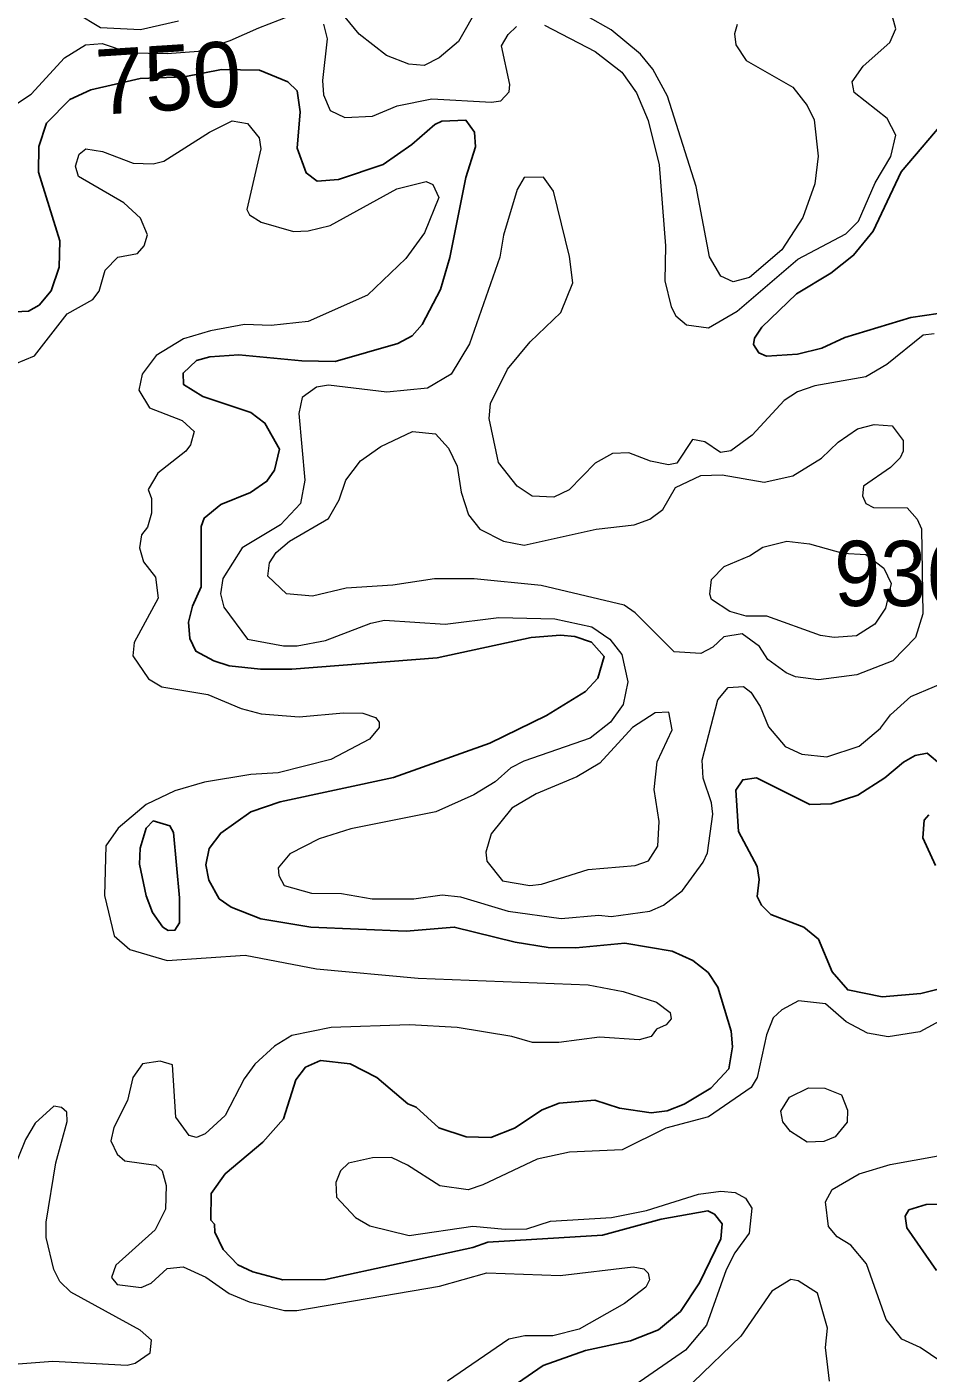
# Model space of a CAD drawing. Extents: x 763.2 to 816.8, y 7896.5 to 7952.7.
# Drawn here: x 772.488 to 774.699, y 7913.666 to 7916.968 of the extents above; entities that cross this region are included whole.
import ezdxf
from ezdxf.enums import TextEntityAlignment as Align

# ---------------------------------------------------------------- set-up
doc = ezdxf.new("R2010")
doc.units = 0
doc.header["$LTSCALE"] = 0.064
doc.layers.add('1', color=7, linetype='Continuous', lineweight=25)
doc.layers.add('2', color=7, linetype='Continuous', lineweight=13)
doc.layers.add('21', color=7, linetype='Continuous')
doc.layers.add('61', color=7, linetype='Continuous')

msp = doc.modelspace()

# ---------------------------------------------------------------- linework, layer by layer
at = {"layer": '1'}
for points in [[(772.8943, 7915.5473), (772.9158, 7915.595), (772.9157, 7915.7428), (772.9231, 7915.7635), (772.9643, 7915.7966), (773.0365, 7915.8265), (773.077, 7915.8539), (773.0953, 7915.881), (773.1079, 7915.9322), (773.0723, 7915.9965), (773.038, 7916.0226), (772.9197, 7916.0616), (772.8726, 7916.091), (772.8715, 7916.1192), (772.9045, 7916.1496), (772.937, 7916.1588), (773.0084, 7916.1635), (773.1629, 7916.1488), (773.2442, 7916.1477), (773.3981, 7916.1913), (773.4337, 7916.2102), (773.4581, 7916.2382), (773.5025, 7916.3238), (773.5254, 7916.4027), (773.5647, 7916.5984), (773.5891, 7916.674), (773.5861, 7916.7101), (773.5651, 7916.739), (773.506, 7916.7366), (773.4886, 7916.7289), (773.4327, 7916.6793), (773.3619, 7916.6302), (773.2529, 7916.5938), (773.2, 7916.5901), (773.1734, 7916.6098), (773.1511, 7916.6709), (773.1588, 7916.7595), (773.1517, 7916.8111), (773.1281, 7916.8336), (773.0593, 7916.8617), (772.9659, 7916.8637), (772.8745, 7916.8459), (772.7663, 7916.8417), (772.6452, 7916.8141), (772.5934, 7916.7901), (772.5363, 7916.7318), (772.518, 7916.6747), (772.5166, 7916.6119), (772.5689, 7916.4431), (772.5672, 7916.379), (772.5476, 7916.3204), (772.5182, 7916.2858), (772.492, 7916.271), (772.4595, 7916.2689)], [(774.7493, 7916.7498), (774.6331, 7916.6123), (774.5638, 7916.467), (774.5159, 7916.4082), (774.4604, 7916.3642), (774.3757, 7916.3135), (774.2907, 7916.232), (774.2732, 7916.2049), (774.2703, 7916.1894), (774.2834, 7916.1683), (774.3021, 7916.1607), (774.3783, 7916.1653), (774.4381, 7916.1804), (774.495, 7916.2063), (774.6562, 7916.2552), (774.7234, 7916.2654)], [(772.9846, 7915.4012), (772.947, 7915.4132), (772.903, 7915.4369), (772.888, 7915.468), (772.8846, 7915.5079), (772.8943, 7915.5473)], [(773.692, 7913.6414), (773.7548, 7913.6849), (773.8589, 7913.7215), (773.9691, 7913.7451), (774.0373, 7913.7722), (774.0912, 7913.8174), (774.1383, 7913.8876), (774.1904, 7913.9953), (774.1936, 7914.0326), (774.1748, 7914.0563), (774.1588, 7914.0647), (774.0438, 7914.0438), (773.9001, 7914.0044), (773.619, 7913.9876), (773.5821, 7913.9746), (773.2206, 7913.8958), (773.1159, 7913.8954), (773.0422, 7913.9148), (773.0061, 7913.932), (772.9698, 7913.9696), (772.949, 7914.0117), (772.9482, 7914.0319), (772.9399, 7914.0411), (772.9403, 7914.1069), (772.9748, 7914.1552), (773.0668, 7914.2327), (773.1174, 7914.2899), (773.1483, 7914.3855), (773.1721, 7914.4164), (773.2089, 7914.4329), (773.2812, 7914.4246), (773.3468, 7914.3915), (773.4224, 7914.3267), (773.443, 7914.3183), (773.4986, 7914.2676), (773.5657, 7914.246), (773.6265, 7914.2442), (773.6847, 7914.2672), (773.7523, 7914.3122), (773.794, 7914.328), (773.8813, 7914.3361), (773.9419, 7914.3163), (774.0193, 7914.305), (774.0586, 7914.3098), (774.1002, 7914.326), (774.1656, 7914.3653), (774.21, 7914.413), (774.2188, 7914.4668), (774.2157, 7914.5046), (774.183, 7914.6132), (774.159, 7914.6485), (774.1219, 7914.6779), (774.0709, 7914.7014), (773.9551, 7914.7206), (773.8352, 7914.7091), (773.7667, 7914.7105), (773.6863, 7914.7234), (773.5368, 7914.7601), (773.4185, 7914.7504), (773.185, 7914.7598), (773.0618, 7914.7804), (772.9896, 7914.8087), (772.9597, 7914.8299), (772.935, 7914.8753), (772.9273, 7914.913), (772.9358, 7914.953), (772.964, 7914.9908), (773.038, 7915.043), (773.1095, 7915.0674), (773.3874, 7915.1271), (773.6239, 7915.2112), (773.7631, 7915.2793), (773.8583, 7915.3382), (773.8887, 7915.3706), (773.9047, 7915.4235), (773.8729, 7915.4588), (773.8326, 7915.4733), (773.7973, 7915.4766), (773.725, 7915.4702), (773.4949, 7915.421), (773.1384, 7915.3928), (773.061, 7915.3928), (772.9846, 7915.4012)], [(774.7319, 7915.1572), (774.6966, 7915.1871), (774.6675, 7915.1807), (774.6386, 7915.1648), (774.5929, 7915.1263), (774.5267, 7915.0842), (774.4611, 7915.0628), (774.4089, 7915.0611), (774.2781, 7915.1264), (774.2442, 7915.1216), (774.2269, 7915.096), (774.2335, 7914.9949), (774.2797, 7914.909), (774.2845, 7914.8769), (774.2797, 7914.8353), (774.2901, 7914.8139), (774.3133, 7914.7912), (774.394, 7914.7604), (774.4302, 7914.7303), (774.4637, 7914.6509), (774.5019, 7914.606), (774.5861, 7914.5893), (774.6807, 7914.5975), (774.8713, 7914.6451)], [(774.7169, 7914.9114), (774.6858, 7914.9788), (774.6889, 7915.0225), (774.7003, 7915.0355)], [(774.9002, 7914.0847), (774.6938, 7914.0796), (774.6518, 7914.0665), (774.6422, 7914.0512), (774.6463, 7914.0225), (774.7191, 7913.9178)]]:
    msp.add_lwpolyline(points, dxfattribs=at)
msp.add_lwpolyline([(772.863, 7914.8316), (772.8479, 7914.9925), (772.8392, 7915.0085), (772.7984, 7915.0208), (772.7807, 7915.0031), (772.7661, 7914.954), (772.7648, 7914.9146), (772.7811, 7914.8367), (772.7967, 7914.7964), (772.822, 7914.7603), (772.8348, 7914.752), (772.8513, 7914.7524), (772.863, 7914.7706)], close=True, dxfattribs=at)
at = {"layer": '2'}
for points in [[(773.5965, 7917.02), (773.547, 7916.9321), (773.4996, 7916.8922), (773.4631, 7916.8737), (773.4251, 7916.8769), (773.3706, 7916.8978), (773.3036, 7916.9506), (773.2346, 7917.0342)], [(774.13, 7916.5767), (774.06, 7916.7983), (774.024, 7916.8642), (773.9937, 7916.9015), (773.9214, 7916.9607), (773.8053, 7917.026)], [(772.4584, 7916.9898), (772.3833, 7916.8678), (772.3753, 7916.8024), (772.3923, 7916.768), (772.4284, 7916.7652), (772.4482, 7916.7699), (772.4987, 7916.8034), (772.5809, 7916.892), (772.6322, 7916.9241), (772.6731, 7916.9276), (772.7408, 7916.9047), (772.8322, 7916.9027), (772.9097, 7916.9087), (772.9872, 7916.9345), (773.057, 7916.9659), (773.1332, 7916.9952)], [(772.8604, 7916.982), (772.767, 7916.9608), (772.6692, 7916.9658), (772.6089, 7917.0017)], [(773.216, 7916.9751), (773.2246, 7916.9385), (773.2132, 7916.8365), (773.2162, 7916.8011), (773.2323, 7916.763), (773.2679, 7916.7455), (773.3363, 7916.7489), (773.3967, 7916.7744), (773.4816, 7916.7914), (773.6276, 7916.7834), (773.6512, 7916.7868), (773.6715, 7916.8086), (773.6733, 7916.827), (773.6524, 7916.9218), (773.6691, 7916.9496), (773.6895, 7916.9691)], [(773.7576, 7916.972), (773.8819, 7916.9081), (773.9479, 7916.8568), (773.9837, 7916.8062), (774.0125, 7916.7384), (774.0396, 7916.6294), (774.0544, 7916.4315), (774.0529, 7916.3454), (774.0688, 7916.2816), (774.0803, 7916.2594), (774.106, 7916.2376), (774.1606, 7916.2296), (774.2304, 7916.2705), (774.3794, 7916.3982), (774.4969, 7916.4604), (774.5281, 7916.4913), (774.5688, 7916.586), (774.6076, 7916.6503), (774.6198, 7916.7023), (774.5982, 7916.7435), (774.5172, 7916.8073), (774.5126, 7916.8332), (774.5395, 7916.872), (774.6049, 7916.9295), (774.6196, 7916.9633), (774.6081, 7917.0048)], [(774.2306, 7916.9736), (774.2237, 7916.9509), (774.2273, 7916.9237), (774.253, 7916.8857), (774.3672, 7916.8201), (774.4019, 7916.7753), (774.4194, 7916.7399), (774.4292, 7916.651), (774.4209, 7916.5828), (774.3914, 7916.5006), (774.3397, 7916.4212)], [(772.5068, 7916.161), (772.5873, 7916.2641), (772.6505, 7916.2998), (772.6656, 7916.32), (772.6806, 7916.3718), (772.7112, 7916.4035), (772.7599, 7916.4122), (772.7758, 7916.4315), (772.7838, 7916.4578), (772.7668, 7916.4991), (772.7264, 7916.5368), (772.615, 7916.6014), (772.6075, 7916.6266), (772.6167, 7916.6563), (772.6328, 7916.6694), (772.6738, 7916.6628), (772.7487, 7916.6335), (772.798, 7916.6322), (772.8241, 7916.6385), (772.936, 7916.7096), (772.992, 7916.7375), (773.0292, 7916.7311), (773.0578, 7916.6958), (773.0619, 7916.6692), (773.0276, 7916.5205), (773.0346, 7916.507), (773.0629, 7916.4895), (773.1424, 7916.4661), (773.178, 7916.4676), (773.2322, 7916.4808), (773.3961, 7916.5713), (773.4677, 7916.5891), (773.4841, 7916.5816), (773.4988, 7916.5493), (773.4637, 7916.4632), (773.418, 7916.3998), (773.3236, 7916.3097), (773.1786, 7916.2459), (773.0872, 7916.236), (773.0222, 7916.2378), (772.9386, 7916.2228), (772.8723, 7916.2027), (772.8056, 7916.162), (772.7713, 7916.1161), (772.7629, 7916.0773), (772.7893, 7916.034), (772.8696, 7916.0024), (772.8988, 7915.9754), (772.8895, 7915.9427), (772.8785, 7915.9278), (772.8099, 7915.8737), (772.7861, 7915.8331), (772.7939, 7915.8111), (772.7938, 7915.7752), (772.784, 7915.7414), (772.7695, 7915.7224), (772.7647, 7915.6907), (772.7743, 7915.6561), (772.8039, 7915.6183), (772.8105, 7915.5669), (772.7511, 7915.458), (772.7483, 7915.4259), (772.7865, 7915.3691), (772.8192, 7915.3495), (772.932, 7915.3303), (773.0136, 7915.2963), (773.0629, 7915.2829), (773.1566, 7915.2761), (773.2647, 7915.286), (773.312, 7915.2845), (773.3431, 7915.2739), (773.3525, 7915.2628), (773.3527, 7915.2496), (773.3286, 7915.2212), (773.2338, 7915.171), (773.1044, 7915.1384), (773.0379, 7915.1348), (772.9244, 7915.1156), (772.8514, 7915.0941), (772.7809, 7915.0607), (772.7119, 7915.0032), (772.6821, 7914.9593), (772.679, 7914.8381), (772.7027, 7914.7391), (772.7412, 7914.7056), (772.8323, 7914.6783), (773.024, 7914.6911), (773.199, 7914.6582), (773.4482, 7914.6353), (773.8648, 7914.6188), (773.951, 7914.6023), (774.0326, 7914.5762), (774.0658, 7914.551), (774.0689, 7914.5352), (774.0565, 7914.5206)], [(773.6455, 7915.8998), (773.6226, 7916.0076), (773.6259, 7916.0443), (773.6672, 7916.1287), (773.723, 7916.1954), (773.798, 7916.2673), (773.8277, 7916.3402), (773.8196, 7916.4046), (773.7804, 7916.5649), (773.7556, 7916.5995), (773.7084, 7916.5991), (773.6911, 7916.569), (773.6577, 7916.4576), (773.648, 7916.4031), (773.5742, 7916.191), (773.5291, 7916.1167), (773.4713, 7916.0817), (773.3714, 7916.072), (773.2279, 7916.0896), (773.1986, 7916.0845), (773.1638, 7916.0593), (773.1556, 7916.0199), (773.1704, 7915.8565), (773.1597, 7915.7992), (773.1101, 7915.7467), (773.016, 7915.6904), (772.9689, 7915.6153), (772.9632, 7915.5773), (772.9714, 7915.5445), (773.0295, 7915.4662), (773.1175, 7915.4502), (773.1509, 7915.4502), (773.2211, 7915.4628), (773.3324, 7915.506), (773.3659, 7915.5128), (773.5145, 7915.503), (773.646, 7915.5194), (773.7833, 7915.5161), (773.8744, 7915.4966), (773.9181, 7915.4668), (773.9475, 7915.4284), (773.9622, 7915.3617), (773.9507, 7915.3061), (773.9196, 7915.2628), (773.8698, 7915.2234), (773.7071, 7915.1674), (773.675, 7915.1512), (773.637, 7915.1168), (773.5849, 7915.0849), (773.4914, 7915.0433), (773.2828, 7915.0009), (773.2053, 7914.977), (773.1332, 7914.9395), (773.1048, 7914.9056), (773.1065, 7914.8869), (773.1196, 7914.8624), (773.1868, 7914.8431), (773.2601, 7914.8423), (773.3349, 7914.8292), (773.4376, 7914.8292), (773.5067, 7914.8391), (773.552, 7914.8343), (773.669, 7914.7994), (773.7992, 7914.7816), (773.8912, 7914.7895), (773.9218, 7914.7865), (774.0167, 7914.7996), (774.0496, 7914.8144), (774.0963, 7914.8496), (774.1474, 7914.9191), (774.1577, 7914.942), (774.1711, 7915.037), (774.1677, 7915.0648), (774.147, 7915.1258), (774.145, 7915.1693), (774.1829, 7915.3173), (774.2088, 7915.3481), (774.2457, 7915.3503), (774.264, 7915.3361), (774.2873, 7915.3015), (774.3077, 7915.2516), (774.3482, 7915.203), (774.3888, 7915.184), (774.4501, 7915.1776), (774.5294, 7915.2039), (774.582, 7915.2482), (774.6068, 7915.2811), (774.6565, 7915.3261), (774.7727, 7915.3748)], [(774.3397, 7916.4212), (774.2604, 7916.3531), (774.2211, 7916.3429), (774.1904, 7916.3563), (774.163, 7916.4043), (774.13, 7916.5767)], [(772.2977, 7916.2738), (772.3195, 7916.2205), (772.3734, 7916.1606), (772.4107, 7916.1421), (772.4596, 7916.1418), (772.5068, 7916.161)], [(774.7134, 7916.2152), (774.6869, 7916.2124), (774.5979, 7916.1403), (774.5459, 7916.1095), (774.4211, 7916.0879), (774.3783, 7916.073), (774.3455, 7916.0518), (774.267, 7915.9669), (774.2149, 7915.9286), (774.1894, 7915.9241), (774.1509, 7915.9502), (774.1209, 7915.9564), (774.0828, 7915.8981), (774.0621, 7915.8942), (774.0177, 7915.9026), (773.9647, 7915.9234), (773.9247, 7915.9218), (773.8825, 7915.8981), (773.8183, 7915.8325), (773.7808, 7915.8146), (773.7277, 7915.8171), (773.6913, 7915.8416), (773.6455, 7915.8998)], [(774.6782, 7914.5037), (774.6011, 7914.4908), (774.5499, 7914.5003), (774.4982, 7914.5276), (774.4475, 7914.5724), (774.3806, 7914.5792), (774.3402, 7914.5572), (774.3192, 7914.5378), (774.3028, 7914.496), (774.2798, 7914.3912), (774.2651, 7914.3666), (774.1606, 7914.2949), (774.0556, 7914.2668), (773.9484, 7914.214), (773.8195, 7914.2079), (773.7399, 7914.1913), (773.6066, 7914.1278), (773.5704, 7914.1162), (773.5014, 7914.1256), (773.4218, 7914.1767), (773.3824, 7914.1948), (773.3363, 7914.1947), (773.2776, 7914.1809), (773.2578, 7914.1623), (773.2462, 7914.1341), (773.248, 7914.0982), (773.2943, 7914.0482), (773.3294, 7914.0276), (773.4258, 7914.0042), (773.5821, 7914.027), (773.6618, 7914.019), (773.715, 7914.0204), (773.7729, 7914.039), (773.9219, 7914.0477), (774.0084, 7914.0655), (774.1357, 7914.1054), (774.1902, 7914.1125), (774.2255, 7914.1091), (774.2511, 7914.0957), (774.2663, 7914.0706), (774.2597, 7914.0094), (774.2247, 7913.9611), (774.2039, 7913.9197), (774.1553, 7913.7837), (774.1042, 7913.7222), (773.9792, 7913.6371)], [(775.1941, 7914.576), (775.0736, 7914.5597), (774.8937, 7914.5889), (774.8445, 7914.5834), (774.7873, 7914.5619), (774.6782, 7914.5037)], [(773.7932, 7914.4775), (773.7282, 7914.4775), (773.6776, 7914.4923), (773.5434, 7914.5136), (773.4272, 7914.5203), (773.2351, 7914.5136), (773.138, 7914.4944), (773.0954, 7914.4684), (773.0476, 7914.4237), (773.0211, 7914.3883), (772.9744, 7914.2981), (772.926, 7914.253), (772.9046, 7914.2444), (772.8867, 7914.2492), (772.8536, 7914.2941), (772.8458, 7914.4224), (772.8155, 7914.4314), (772.772, 7914.4251), (772.7482, 7914.3917), (772.7348, 7914.3346), (772.702, 7914.2687), (772.694, 7914.2356), (772.7099, 7914.2037), (772.7286, 7914.1868), (772.805, 7914.1765), (772.8198, 7914.1621), (772.8301, 7914.1267), (772.8285, 7914.0683), (772.803, 7914.0179), (772.7069, 7913.9314), (772.6958, 7913.9007), (772.7097, 7913.8838), (772.7683, 7913.876), (772.7936, 7913.8873), (772.8328, 7913.923), (772.8719, 7913.9269), (772.927, 7913.902), (772.9847, 7913.8614), (773.0339, 7913.8415), (773.1205, 7913.8201), (773.1508, 7913.8202), (773.5007, 7913.8793), (773.6163, 7913.9121), (773.7965, 7913.9056), (773.9755, 7913.9268), (774.0012, 7913.9221), (774.012, 7913.9113), (774.0159, 7913.8952), (774.0062, 7913.8774), (773.9538, 7913.8374), (773.8431, 7913.7744), (773.7782, 7913.7579), (773.7097, 7913.7575), (773.6705, 7913.7495), (773.5201, 7913.6465)], [(774.0565, 7914.5206), (774.033, 7914.5096), (774.0192, 7914.4922), (773.9904, 7914.4841), (773.8925, 7914.4906), (773.7932, 7914.4775)], [(772.321, 7913.6366), (772.3767, 7913.6672), (772.4566, 7913.6882), (772.5523, 7913.6953), (772.7341, 7913.6854), (772.7543, 7913.6903), (772.7907, 7913.7157), (772.7938, 7913.7469), (772.7663, 7913.7719), (772.5963, 7913.8649), (772.5689, 7913.891), (772.5541, 7913.9204), (772.536, 7913.9992), (772.5357, 7914.0364), (772.5597, 7914.1823), (772.587, 7914.2836), (772.5864, 7914.3067), (772.5736, 7914.3179), (772.5543, 7914.321), (772.509, 7914.2797), (772.4851, 7914.2392), (772.4287, 7914.0998), (772.4162, 7914.0426)], [(774.7299, 7913.6951), (774.6796, 7913.7293), (774.6348, 7913.7498), (774.5961, 7913.7978), (774.5478, 7913.9346), (774.5092, 7913.9801), (774.4756, 7914.0004), (774.4546, 7914.0262), (774.4476, 7914.0862), (774.4635, 7914.117), (774.5296, 7914.1553), (774.6057, 7914.1777), (774.7917, 7914.2111)], [(774.4572, 7913.6466), (774.4474, 7913.729), (774.4521, 7913.7764), (774.4272, 7913.8627), (774.3798, 7913.8923), (774.3623, 7913.8958), (774.3157, 7913.8669), (774.2397, 7913.7572), (774.123, 7913.6438)]]:
    msp.add_lwpolyline(points, dxfattribs=at)
for points in [[(773.8846, 7915.7361), (773.9781, 7915.7466), (774.0161, 7915.7608), (774.0478, 7915.7842), (774.0796, 7915.8381), (774.1415, 7915.8677), (774.1935, 7915.8692), (774.2971, 7915.8515), (774.3673, 7915.8674), (774.4374, 7915.9107), (774.4786, 7915.9499), (774.5257, 7915.9824), (774.5663, 7915.9927), (774.6105, 7915.99), (774.6374, 7915.9535), (774.6375, 7915.9272), (774.6305, 7915.9115), (774.6066, 7915.8875), (774.54, 7915.8416), (774.5379, 7915.8176), (774.546, 7915.7995), (774.5653, 7915.7893), (774.6472, 7915.7888), (774.6723, 7915.761), (774.6823, 7915.7373), (774.6856, 7915.5287), (774.6681, 7915.4701), (774.6121, 7915.4135), (774.5243, 7915.3787), (774.4302, 7915.3666), (774.374, 7915.3743), (774.3508, 7915.3838), (774.3061, 7915.4164), (774.285, 7915.4482), (774.2429, 7915.4798), (774.1981, 7915.4719), (774.1707, 7915.4469), (774.1416, 7915.4309), (774.076, 7915.4356), (773.98, 7915.5313), (773.9531, 7915.5501), (773.7494, 7915.5979), (773.5854, 7915.6147), (773.4882, 7915.6147), (773.3863, 7915.5985), (773.2713, 7915.5917), (773.1891, 7915.5722), (773.1255, 7915.5778), (773.079, 7915.6208), (773.0834, 7915.6539), (773.0997, 7915.6788), (773.1325, 7915.7067), (773.2279, 7915.7626), (773.2542, 7915.8079), (773.2708, 7915.8564), (773.3063, 7915.9034), (773.3567, 7915.9388), (773.4343, 7915.9759), (773.4903, 7915.9697), (773.5221, 7915.9348), (773.5441, 7915.8904), (773.5533, 7915.8268), (773.5712, 7915.7715), (773.5996, 7915.7363), (773.6578, 7915.707), (773.7077, 7915.697)], [(774.2932, 7915.6921), (774.352, 7915.7066), (774.4078, 7915.7), (774.4894, 7915.6774), (774.5458, 7915.6737), (774.59, 7915.6409), (774.6081, 7915.6032), (774.5945, 7915.5425), (774.5686, 7915.5028), (774.5229, 7915.4742), (774.4687, 7915.4701), (774.4347, 7915.475), (774.3029, 7915.5227), (774.2524, 7915.5228), (774.2128, 7915.5341), (774.1676, 7915.5635), (774.1634, 7915.577), (774.1677, 7915.6128), (774.1987, 7915.645), (774.2606, 7915.6711)], [(774.0267, 7915.0977), (774.0347, 7915.1654), (774.071, 7915.2439), (774.0628, 7915.2871), (774.0295, 7915.2856), (773.9741, 7915.25), (773.8938, 7915.162), (773.8373, 7915.1289), (773.7374, 7915.0871), (773.6778, 7915.0521), (773.6274, 7914.9886), (773.6144, 7914.9441), (773.6162, 7914.9221), (773.655, 7914.874), (773.7219, 7914.862), (773.7504, 7914.8654), (773.8649, 7914.9012), (773.9806, 7914.9115), (774.0129, 7914.923), (774.0359, 7914.9584), (774.0396, 7915.0189)], [(774.3614, 7914.259), (774.3424, 7914.2827), (774.3375, 7914.3087), (774.3592, 7914.3427), (774.4053, 7914.3657), (774.4452, 7914.3654), (774.4867, 7914.3485), (774.5013, 7914.3115), (774.5002, 7914.2821), (774.4706, 7914.2462), (774.4434, 7914.2343), (774.4024, 7914.2327)]]:
    msp.add_lwpolyline(points, close=True, dxfattribs=at)

# ---------------------------------------------------------------- texts
at = {"layer": '21', "width": 0.95}
msp.add_text('936', height=0.16, dxfattribs=at).set_placement((774.4683, 7915.5477))
at = {"layer": '61'}
msp.add_text('750', height=0.16, rotation=3.657, dxfattribs=at).set_placement((772.8406, 7916.7635), align=Align.CENTER)

doc.saveas('drawing.dxf')
